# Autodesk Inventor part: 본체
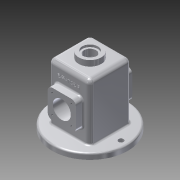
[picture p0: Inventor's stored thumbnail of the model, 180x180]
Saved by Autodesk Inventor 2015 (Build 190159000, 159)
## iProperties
Created: 2021-08
Part Number: 본체
Material: 알루미늄 6061
Document SubType Name: Modeling
Designer: 104-1
Density: 2.7 g/cm^3
Appearance: 알루미늄 - 평지
Mass: 822.027 g
Surface Area: 962.051 cm^2
Volume: 304.454 cm^3
Author: 104-1
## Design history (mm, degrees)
sketch "스케치1"
  geometry: L1 (37, 37)-(-37, 37); L2 (-37, 37)-(-37, -37); L3 (-37, -37)-(37, -37); L4 (37, -37)-(37, 37); L5 (37, 37)-(-37, -37); L6 (-37, 37)-(37, -37); 1 further point
  constraints: 12 end point, 2 midpoint, 2 parallel, 1 horizontal, 1 perpendicular
  dimensions: "d0" = 74 distance of L2.end L3.end; "d1" = 74 distance of L3.end L1.start
extrude "돌출1" new body sketch "스케치1" distance "d2" = 110; taper "d3" = 0 deg
fillet "모깎기1" dims "d4" = 8
fillet "모깎기2" dims "d5" = 8
feature "쉘1" dims "d6" = 5
sketch "스케치2"
  geometry: L1 (-29, 37)-(29, 37) reference; L2 (-37, -29)-(-37, 29) reference; L3 (29, -37)-(-29, -37) reference; L4 (37, 29)-(37, -29) reference; C1 r 67 at (0, 0); A1 r 8 centre (29, 29) between (37, 29) and (29, 37) reference; A2 r 8 centre (-29, 29) between (-29, 37) and (-37, 29) reference; A3 r 8 centre (-29, -29) between (-37, -29) and (-29, -37) reference; A4 r 8 centre (29, -29) between (29, -37) and (37, -29) reference; 1 further point
  constraints: 1 centre point, 1 coincident
  dimensions: "d7" = 134 diameter of C1
extrude "돌출2" join sketch "스케치2" distance "d8" = 10; taper "d9" = 0 deg
sketch "스케치3"
  geometry: L1 (54, -22)-(4, -22); L2 (4, -22)-(4, -72); L3 (4, -72)-(54, -72); L4 (54, -72)-(54, -22); L5 (54, -22)-(4, -72); L6 (4, -22)-(54, -72); L7 (96, -102)-(-38, -102) reference; 4 further points
  constraints: 12 end point, 4 midpoint, 2 parallel, 1 horizontal, 1 perpendicular, 1 vertical alignment
  dimensions: "d10" = 55 distance from line of L7 point (29, -47); "d61" = 50 distance of L1.end L2.end; "d62" = 50 distance of L2.end L3.end
extrude "돌출3" join sketch "스케치3" distance "d11" = 13; taper "d13" = 0 deg; dims "d12" = 12, "d14" = 0
chamfer "모따기1" distance "d15" = 7; stored, may be unused: second distance "d16" = 2, angle "d17" = 45 deg
chamfer "모따기2" distance "d18" = 7; stored, may be unused: second distance "d19" = 2, angle "d20" = 45 deg
chamfer "모따기3" distance "d21" = 7; stored, may be unused: second distance "d22" = 2, angle "d23" = 45 deg
chamfer "모따기4" distance "d24" = 7; stored, may be unused: second distance "d25" = 2, angle "d26" = 45 deg
chamfer "모따기5" distance "d27" = 7; stored, may be unused: second distance "d28" = 2, angle "d29" = 45 deg
chamfer "모따기6" distance "d30" = 7; stored, may be unused: second distance "d31" = 2, angle "d32" = 45 deg
chamfer "모따기7" distance "d33" = 7; stored, may be unused: second distance "d34" = 2, angle "d35" = 45 deg
fillet "모깎기3" dims "d36" = 8
fillet "모깎기4" dims "d37" = 8
chamfer "모따기8" distance "d38" = 7; stored, may be unused: second distance "d39" = 2, angle "d40" = 45 deg
sketch "스케치4"
  geometry: C1 r 67 at (0, 0) reference; 1 further point
  constraints: 1 horizontal alignment
  dimensions: "d41" = 55 distance of C1.centre point (-55, 0)
hole "구멍1" sketch "스케치4" at (-55, 0) diameter "d42" = 9; stored, may be unused: countersink angle "d46" = 90 deg, drill point angle "d48" = 118 deg; dims "d43" = 6, "d44" = 4, "d45" = 2, "d47" = 8
sketch "스케치5"
  geometry: L1 (96, -102)-(-38, -102) reference; L2 (-8, 0)-(-8, -92) reference; 2 further points
  dimensions: "d52" = 55 distance from line of L1 point (29, -47); "d53" = 37 distance from line of L2 point (29, -47)
hole "구멍2" sketch "스케치5" at (29, -47) diameter "d54" = 32; stored, may be unused: countersink angle "d58" = 90 deg, drill point angle "d60" = 118 deg; dims "d55" = 6, "d56" = 4, "d57" = 2, "d59" = 8
sketch "스케치6"
  geometry: A1 r 8 centre (34, -42) between (34, -50) and (42, -42) reference; A2 r 8 centre (34, -8) between (42, -8) and (34, 0) reference; A3 r 8 centre (0, -8) between (0, 0) and (-8, -8) reference; A4 r 8 centre (0, -42) between (-8, -42) and (0, -50) reference; 1 further point
hole "구멍3" sketch "스케치6" at (34, -42), (0, -8), (34, -8), (0, -42) diameter "d63" = 3.242; stored, may be unused: countersink angle "d67" = 90 deg, drill point angle "d69" = 118 deg; dims "d64" = 8, "d65" = 4, "d66" = 2, "d68" = 10
node "작업 평면1"
sketch "스케치8"
  geometry: L1 (29, 29)-(29, -29) reference; L2 (-29, 29)-(29, 29) reference; L3 (-29, -29)-(-29, 29) reference; L4 (29, -29)-(-29, -29) reference; L5 (37, -29)-(37, 29) reference; L6 (29, 37)-(-29, 37) reference; L7 (-37, 29)-(-37, -29) reference; L8 (-29, -37)-(29, -37) reference; C1 r 20 at (0, 0); 1 further point
  constraints: 1 centre point, 1 coincident
  dimensions: "d71" = 40 diameter of C1
extrude "돌출4" join sketch "스케치8" stored distance "d72" = 13; taper "d73" = 0 deg
sketch "스케치9"
  geometry: C1 r 20 at (0, 0) reference
hole "구멍4" sketch "스케치9" at (0, 0) diameter "d74" = 21; stored, may be unused: countersink angle "d78" = 90 deg, drill point angle "d80" = 0 deg; dims "d75" = 8, "d76" = 28, "d77" = 4, "d79" = 10
sketch "스케치10"
  geometry: L1 (-8, 0)-(-8, -92) reference; L2 (9, 18)-(49, 18) reference; 2 further points
  constraints: 1 other
  dimensions: "d81" = 37 distance from line of point (29, -10) L1; "d82" = 28 distance from line of point (29, -10) L2
feature "엠보싱1" sketch "스케치10" dims "d83" = 0.5, "d84" = 0
fillet "모깎기5" dims "d85" = 3
fillet "모깎기6" dims "d86" = 3
fillet "모깎기7" dims "d87" = 3
fillet "모깎기8" dims "d88" = 3
node "솔리드1"
mirror "대칭1"
pattern_circular "원형 패턴1" dims angle "d50" = 360 deg
mirror "대칭2"
node "투영된 루프1"
